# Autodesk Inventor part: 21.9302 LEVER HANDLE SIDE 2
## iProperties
Created: 2011-01
Part Number: 21.9302 LEVER HANDLE SIDE 2
Document SubType Name: Modeling
Designer: Administrator
Density: 7.85 g/cm^3
Material: Steel
Mass: 236.292 g
Surface Area: 87.4619 cm^2
Volume: 30.1009 cm^3
Author: Administrator
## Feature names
1. Extrusion1
2. Extrusion2
3. Extrusion3
4. Extrusion4
5. Fillet1
6. Extrusion6
7. Extrusion8
8. Fillet7
9. Fillet8
10. Fillet9
11. Fillet10
